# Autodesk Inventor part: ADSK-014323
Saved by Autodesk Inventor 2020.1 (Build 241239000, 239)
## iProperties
Part Number: ADSK-014323
Material: Allgemein
Description: Framegenerator-Skeleton-Referenz
Document SubType Name: Modellieren
Designer: lutzd
Density: 1 g/cm^3
Appearance: Vorgabe
DocNumber: ADSK-014323
Folder: .
Dimensions: 0x0x0 mm
Mass: 0 kg
_SkeletonDoc: Frame Skeleton File
_Version: 15.0.0
Title: Gestellrahmenbauteil(e)
Author: lutzd
Revision Number: -
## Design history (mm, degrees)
sketch "Referenzrahmen"
node "Volumenkörper"
node "Flächenkörper"
